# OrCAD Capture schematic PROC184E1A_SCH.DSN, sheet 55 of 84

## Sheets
55 59. MCU GB ETHERNET: size C; title: MCU GB ETHERNET; note: PROC184_SCH
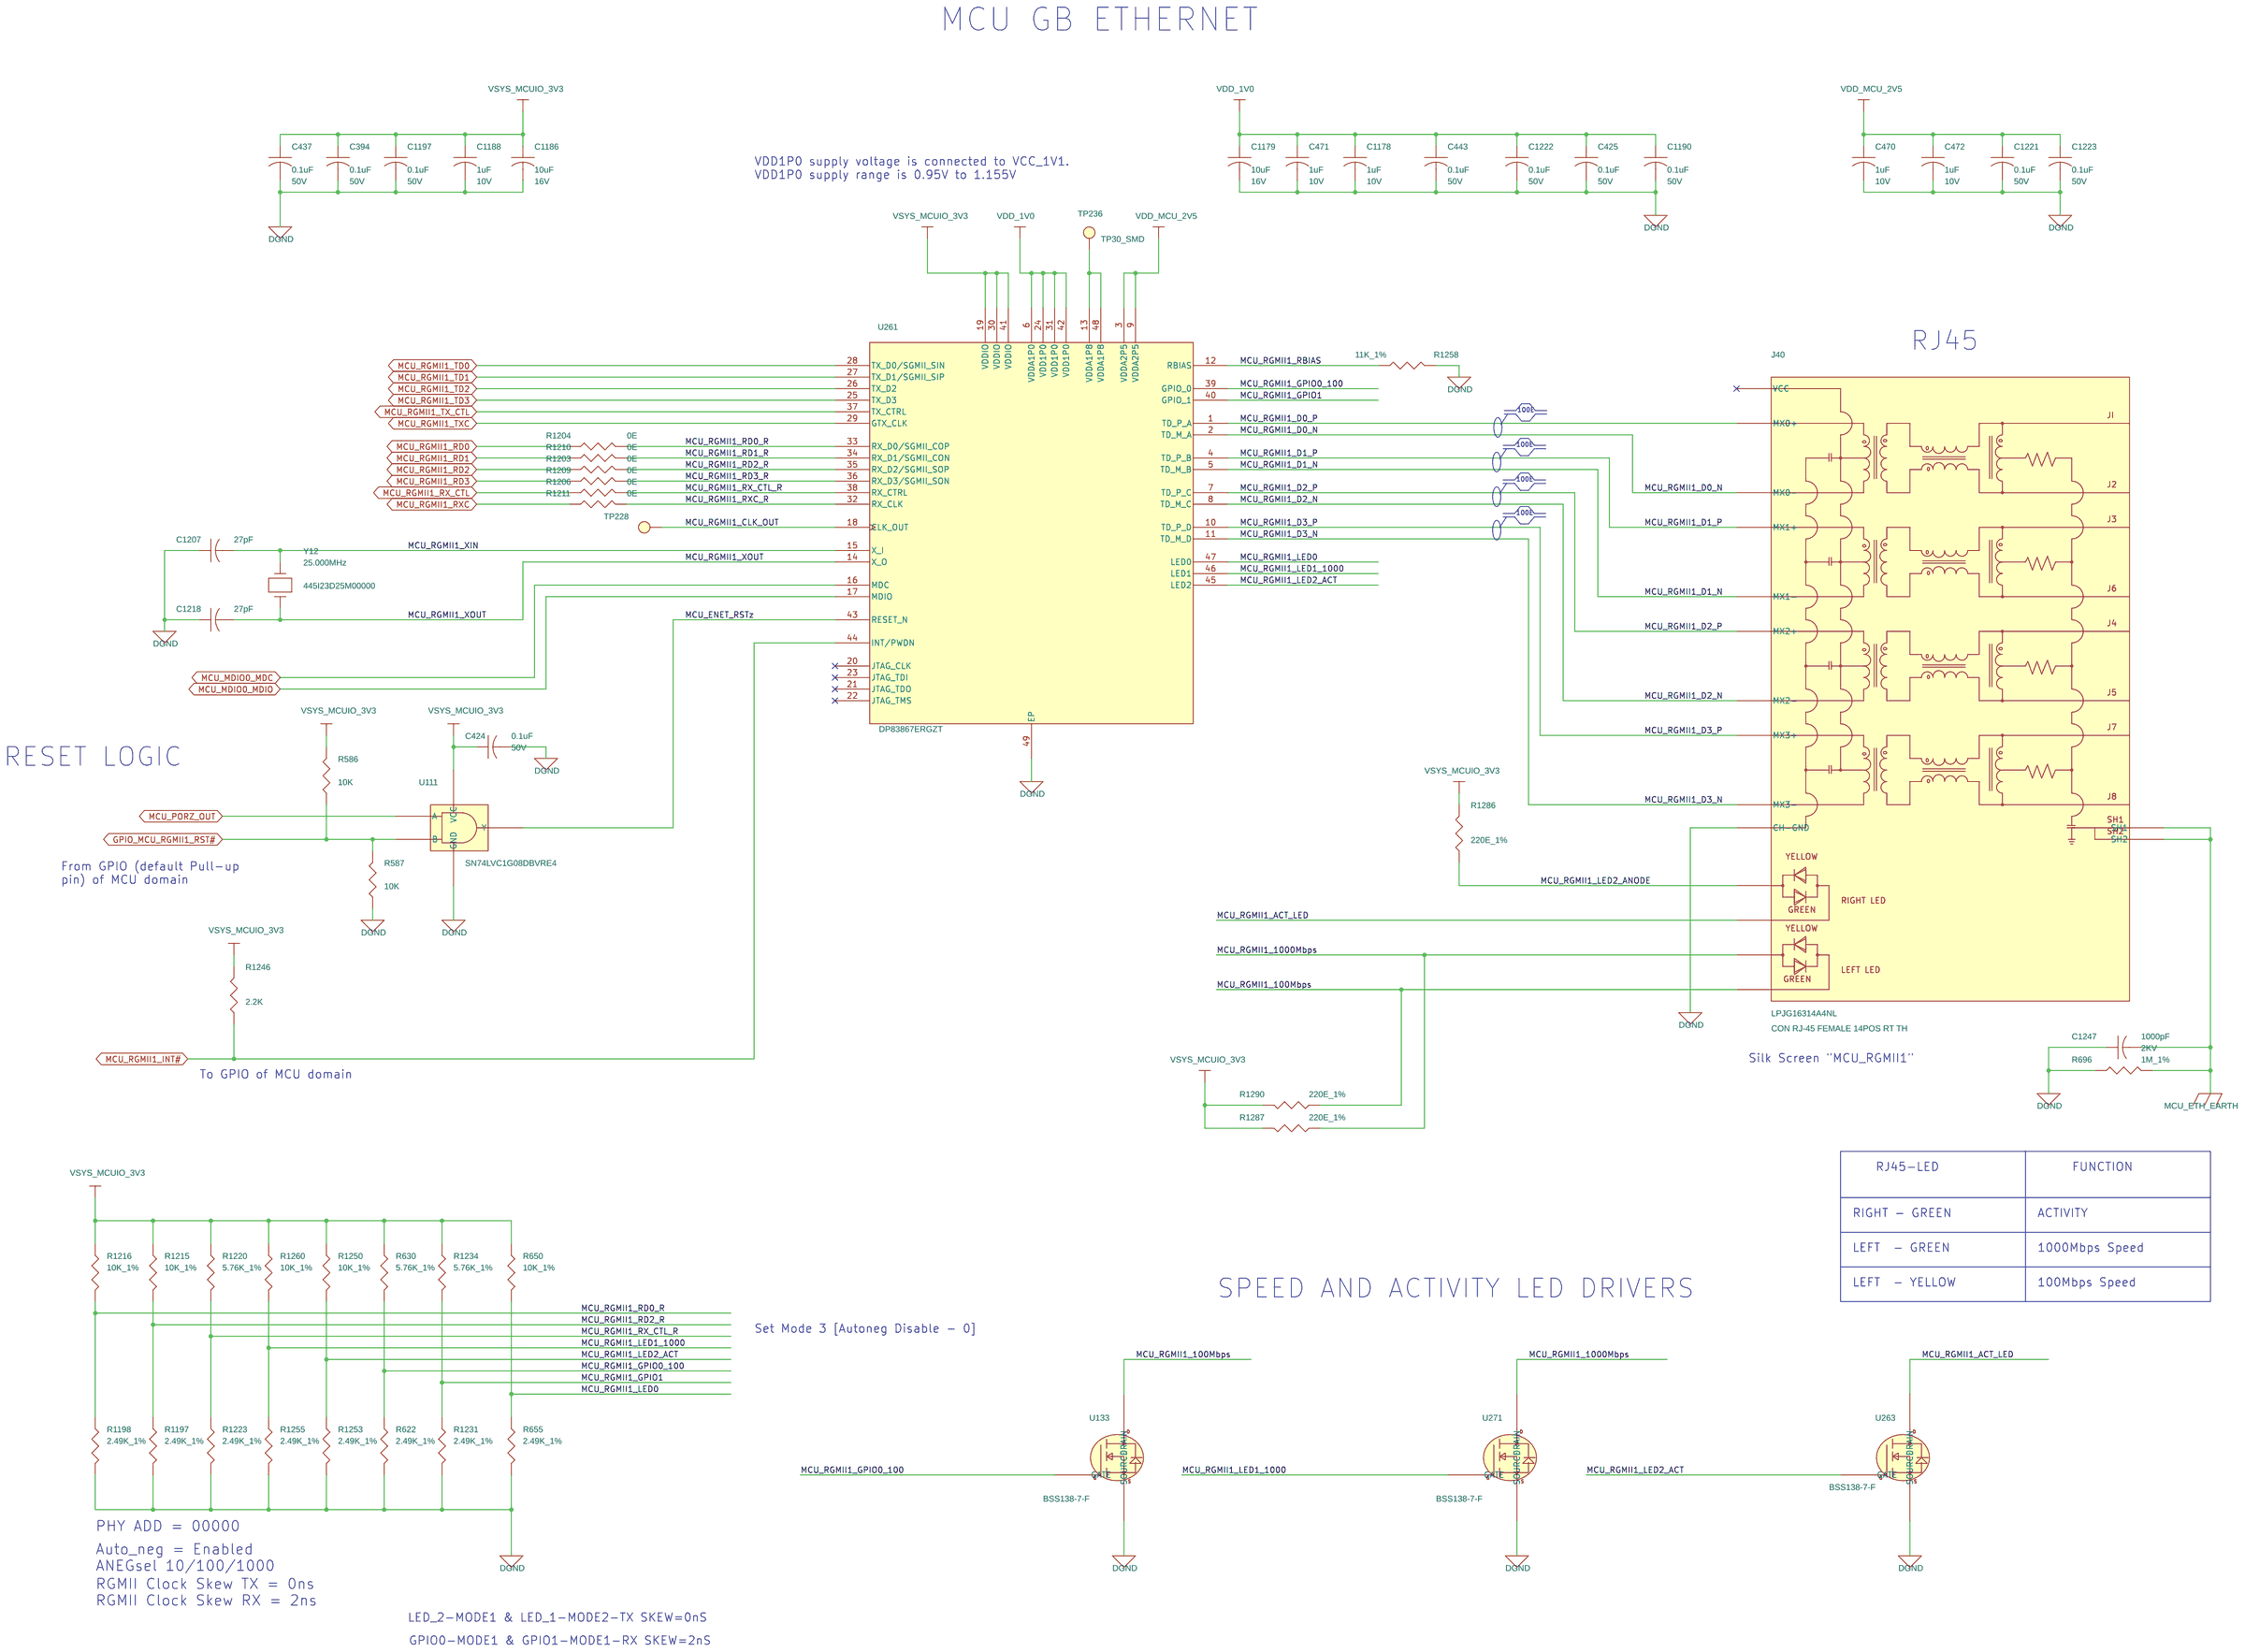
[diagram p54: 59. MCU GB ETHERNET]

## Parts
C394  0.1uF  [CAP0402_0-75]
C424  0.1uF  [CAP0402_0-75]
C425  0.1uF  [CAP0402_0-75]
C437  0.1uF  [CAP0402_0-75]
C443  0.1uF  [CAP0402_0-75]
C470  1uF  [CAP0402_0-75]
C471  1uF  [CAP0402_0-75]
C472  1uF  [CAP0402_0-75]
C1178  1uF  [CAP0402_0-75]
C1179  10uF  [CAP0805_1-5]
C1186  10uF  [CAP0805_1-5]
C1188  1uF  [CAP0402_0-75]
C1190  0.1uF  [CAP0402_0-75]
C1197  0.1uF  [CAP0402_0-75]
C1207  27pF  [CAP0402_0-75]
C1218  27pF  [CAP0402_0-75]
C1221  0.1uF  [CAP0402_0-75]
C1222  0.1uF  [CAP0402_0-75]
C1223  0.1uF  [CAP0402_0-75]
C1247  1000pF  [CAP1206_1-75]
J40  CON_RJ45-14_LPJG16314A4NL  [CON_RJ45-14_LPJG16314A4NL_S_R_T_13-6]
R586  10K  [RES0402_0-5]
R587  10K  [RES0402_0-5]
R622  2.49K_1%  [RES0402_0-5]
R630  5.76K_1%  [RES0402_0-5]
R650  10K_1%  [RES0402_0-5]
R655  2.49K_1%  [RES0402_0-5]
R696  1M_1%  [RES0805_0-75]
R1197  2.49K_1%  [RES0402_0-5]
R1198  2.49K_1%  [RES0402_0-5]
R1203  0E  [RES0201_0-5]
R1204  0E  [RES0201_0-5]
R1206  0E  [RES0201_0-5]
R1209  0E  [RES0201_0-5]
R1210  0E  [RES0201_0-5]
R1211  0E  [RES0201_0-5]
R1215  10K_1%  [RES0402_0-5]
R1216  10K_1%  [RES0402_0-5]
R1220  5.76K_1%  [RES0402_0-5]
R1223  2.49K_1%  [RES0402_0-5]
R1231  2.49K_1%  [RES0402_0-5]
R1234  5.76K_1%  [RES0402_0-5]
R1246  2.2K  [RES0402_0-5]
R1250  10K_1%  [RES0402_0-5]
R1253  2.49K_1%  [RES0402_0-5]
R1255  2.49K_1%  [RES0402_0-5]
R1258  11K_1%  [RES0402_0-5]
R1260  10K_1%  [RES0402_0-5]
R1286  220E_1%  [RES0402_0-5]
R1287  220E_1%  [RES0402_0-5]
R1290  220E_1%  [RES0402_0-5]
TP228  TP30_SMD  [TP30_SMD]
TP236  TP30_SMD  [TP30_SMD]
U111  SN74LVC1G08DBVRE4  [SOT23-5]
U133  BSS138-7-F  [SOT23-123_1-1]
U261  DP83867ERGZT  [VQFN48_19-68_285X285]
U263  BSS138-7-F  [SOT23-123_1-1]
U271  BSS138-7-F  [SOT23-123_1-1]
Y12  25.000MHz  [XTAL_ABM3_205X130_SMD_1-4]

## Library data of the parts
C394 C424 C425 C437 C443 C1190 C1197 C1221-C1223 = CAP: CAP CERAMIC 0.1uF 50V 10% X7R 0402; Automotive Alternate_mfr_name: TDK; Automotive Alternate_mfr_part_number: CGA2B3X7R1H104K050BB; Chkd/date: MANIRAJA/261020; Crtd /date: ALVY/211020; Custom_Duty: 15%; Customs_HS_Code: 85322990; Direct Alternate_mfr_name: TDK; Direct Alternate_mfr_part_number: C1005X7R1H104K050BE; Distributor_name: DIGIKEY; Distributor_part_number: 490-10700-1-ND; Footprint Path: Y:\MIS_DATABASE\Library\ALTIUM_TOOL\PCB_FOOTPRINTS\Altium_Footprint_Lib.PcbLib; Height: 0.55MM; Library Path: Y:\MIS_DATABASE\Library\ALTIUM_TOOL\SCHEMATICS_PARTS\MS_DISCRETE_Library.schlib; Manufacturer: MURATA; Mfr_name: MURATA; Mfr_part_number: GRM155R71H104KE14D; Mistral Part No: 120011100014-R; Package: 0402; Part_type: CAPACITORS\CERAMIC; Project: J7_CP; RoHS: RoHS; Temperature: -55°C+125°C; Tolerance: 10%; Voltage: 50V; Wattage: NA; Weight: 3.1mg; Datasheet: Y:\MIS_DATABASE\DATASHEETS\CAPACITORS\GRM155R71H104KE14.PDF
C470-C472 C1178 C1188 = CAP: CAP CERAMIC 1uF 10V 10% X7S AUTO 0402; Automotive Alternate_mfr_name: TAIYO YUDEN; Automotive Alternate_mfr_part_number: EMK105BJ105KVHF; Chkd/date: MANIRAJA/100918; Crtd /date: ALVY/100918; Custom_Duty: 15%; Customs_HS_Code: 85322990; Direct Alternate_mfr_name: YAGEO AMERICA; Direct Alternate_mfr_part_number: CC0402KRX5R7BB105; Distributor_name: DIGIKEY; Distributor_part_number: 490-13409-1-ND; Footprint Path: Y:\MIS_DATABASE\Library\ALTIUM_TOOL\PCB_FOOTPRINTS\Altium_Footprint_Lib.PcbLib; Height: 0.70MM; Library Path: Y:\MIS_DATABASE\Library\ALTIUM_TOOL\SCHEMATICS_PARTS\MS_DISCRETE_Library.schlib; Manufacturer: TDK CORPORATION; Mfr_name: MURATA; Mfr_part_number: GCM155C71A105KE38D; Mistral Part No: 120018090021-R; Package: 0402; Part_type: CAPACITORS\CERAMIC; Project: SMART-M_SCRIPTALK_PB; RoHS: RoHS; Temperature: -55°C+125°C; Tolerance: 10%; Voltage: 10V; Wattage: NA; Weight: 6mg; Datasheet: Y:\MIS_DATABASE\DATASHEETS\CAPACITORS\MURATA-GCM-SER.PDF
C1179 C1186 = CAP: CAP CERAMIC 10uF 16V 10% X5R 0805; Automotive Alternate_mfr_name: TDK; Automotive Alternate_mfr_part_number: CGA4J1X7S1C106K125AC; Chkd/date: SHREESHAIL/220506; Crtd /date: MAZHAR/150506; Custom_Duty: 15%; Customs_HS_Code: 85322990; Direct Alternate_mfr_name: TDK; Direct Alternate_mfr_part_number: C2012X7S1C106K125AC; Distributor_name: DIGIKEY; Distributor_part_number: 490-3886-1-ND; Footprint Path: Y:\MIS_DATABASE\Library\ALTIUM_TOOL\PCB_FOOTPRINTS\Altium_Footprint_Lib.PcbLib; Height: 1.35MM; Library Path: Y:\MIS_DATABASE\Library\ALTIUM_TOOL\SCHEMATICS_PARTS\MS_DISCRETE_Library.schlib; Manufacturer: MURATA; Mfr_name: MURATA; Mfr_part_number: GRM21BR61C106KE15L; Mistral Part No: 120009030205-R; Package: 0805; Part_type: CAPACITORS\CERAMIC; Project: VOCERA; RoHS: RoHS; Temperature: -55°C+85°C; Tolerance: 10%; Voltage: 16V; Wattage: NA; Weight: 9.5mg; Datasheet: Y:\MIS_DATABASE\DATASHEETS\CAPACITORS\MURATA-GXX-SER_NOV17.PDF
C1207 C1218 = CAP: CAP CERAMIC 27pF 50V 5% C0G(NP0) 0402; Automotive Alternate_mfr_name: TDK; Automotive Alternate_mfr_part_number: CGA2B2C0G1H270J050BA; Chkd/date: MAZHAR/241208; Crtd /date: GEETHA/090606; Custom_Duty: 15%; Customs_HS_Code: 85322990; Direct Alternate_mfr_name: SAMSUNG; Direct Alternate_mfr_part_number: CL05C270JB5NNNC; Distributor_name: DIGIKEY; Distributor_part_number: 311-1019-1-ND; Footprint Path: Y:\MIS_DATABASE\Library\ALTIUM_TOOL\PCB_FOOTPRINTS\Altium_Footprint_Lib.PcbLib; Height: 0.55MM; Library Path: Y:\MIS_DATABASE\Library\ALTIUM_TOOL\SCHEMATICS_PARTS\MS_DISCRETE_Library.schlib; Manufacturer: YAGEO AMERICA; Mfr_name: YAGEO AMERICA; Mfr_part_number: CC0402JRNPO9BN270; Mistral Part No: 120014100024-R; Package: 0402; Part_type: CAPACITORS\CERAMIC; Project: PNAV; RoHS: RoHS; Temperature: -55°C+125°C; Tolerance: 5%; Voltage: 50V; Wattage: NA; Weight: 0.65mg; Datasheet: Y:\MIS_DATABASE\DATASHEETS\CAPACITORS\YACC-NPO.PDF
C1247 = CAP: CAP CERAMIC 1000pF 2KV 10% X7R 1206; Automotive Alternate_mfr_name: KEMET; Automotive Alternate_mfr_part_number: C1206X102KGRACAUTO; Chkd/date: SHREESHAIL/291106; Crtd /date: MAZHAR/281106; Custom_Duty: 15%; Customs_HS_Code: 85322990; Direct Alternate_mfr_name: KEMET; Direct Alternate_mfr_part_number: C1206C102KGRACTU; Distributor_name: DIGIKEY; Distributor_part_number: 478-2956-1-ND; Footprint Path: Y:\MIS_DATABASE\Library\ALTIUM_TOOL\PCB_FOOTPRINTS\Altium_Footprint_Lib.PcbLib; Height: 1.52MM; Library Path: Y:\MIS_DATABASE\Library\ALTIUM_TOOL\SCHEMATICS_PARTS\MS_DISCRETE_Library.schlib; Manufacturer: AVX CORPORATION; Mfr_name: AVX CORPORATION; Mfr_part_number: 1206GC102KAT1A; Mistral Part No: 120015080006-R; Package: 1206; Part_type: CAPACITORS\CERAMIC; Project: ADR1B; RoHS: RoHS; Temperature: -55°C+125°C; Tolerance: 10%; Voltage: 2KV; Wattage: NA; Weight: 16.2mg; Datasheet: Y:\MIS_DATABASE\DATASHEETS\CAPACITORS\AVX_HV-MLC.PDF
J40 = CON_RJ45-14_LPJG16314A4NL: CON RJ-45 FEMALE 14POS RT TH; Chkd/date: VASANTHA/150714; Crtd /date: BALACHANDAR/120614; Custom_Duty: 24%; Customs_HS_Code: 85369090; Distributor_name: NA; Distributor_part_number: NA; Footprint Path: Y:\MIS_DATABASE\Library\ALTIUM_TOOL\PCB_FOOTPRINTS\Altium_Footprint_Lib.PcbLib; Height: 13.60MM; Library Path: Y:\MIS_DATABASE\Library\ALTIUM_TOOL\SCHEMATICS_PARTS\MS_CONNECTOR_Library.schlib; Manufacturer: LINK-PP; Mfr_name: LINK-PP; Mfr_part_number: LPJG16314A4NL; Mistral Part No: 150014060029-R; Package: THRU-HOLE; Part_type: CONNECTOR\JACK; Project: AEGIS; RoHS: RoHS; Temperature: -0°C+70°C; Tolerance: NA; Voltage: NA; Wattage: NA; Weight: NA; Datasheet: Y:\MIS_DATABASE\DATASHEETS\CONNECTORS\LPJG16314A4NL.PDF
R586 = RESISTOR: RES 10K 1/16W 5% 0402; Chkd/date: VASANTHA/061216; Crtd /date: MAZHAR/230805; Custom_Duty: 15%; Customs_HS_Code: 85332119; Distributor_name: DIGIKEY; Distributor_part_number: 311-10KJRCT-ND; Footprint Path: Y:\MIS_DATABASE\Library\ALTIUM_TOOL\PCB_FOOTPRINTS\Altium_Footprint_Lib.PcbLib; Height: 0.40MM; Library Path: Y:\MIS_DATABASE\Library\ALTIUM_TOOL\SCHEMATICS_PARTS\MS_DISCRETE_Library.schlib; Manufacturer: YAGEO AMERICA; Mfr_name: YAGEO AMERICA; Mfr_part_number: RC0402JR-0710KL; Mistral Part No: 110011060021-R; Package: 0402; Part_type: RESISTORS\FIXED; Project: HSE; RoHS: RoHS; Temperature: -55°C+155°C; Tolerance: 5%; Voltage: NA; Wattage: 1/16W; Weight: 0.65mg; Datasheet: Y:\MIS_DATABASE\DATASHEETS\RESISTORS\RCXXXXL-SER_MAR18.PDF
R587 = RESISTOR: RES 10K 1/16W 5% 0402; Assembly_Instruction: DNI; Chkd/date: VASANTHA/061216; Crtd /date: MAZHAR/230805; Custom_Duty: 15%; Customs_HS_Code: 85332119; Distributor_name: DIGIKEY; Distributor_part_number: 311-10KJRCT-ND; Footprint Path: Y:\MIS_DATABASE\Library\ALTIUM_TOOL\PCB_FOOTPRINTS\Altium_Footprint_Lib.PcbLib; Height: 0.40MM; Library Path: Y:\MIS_DATABASE\Library\ALTIUM_TOOL\SCHEMATICS_PARTS\MS_DISCRETE_Library.schlib; Manufacturer: YAGEO AMERICA; Mfr_name: YAGEO AMERICA; Mfr_part_number: RC0402JR-0710KL; Mistral Part No: 110011060021-R; Package: 0402; Part_type: RESISTORS\FIXED; Project: HSE; RoHS: RoHS; Temperature: -55°C+155°C; Tolerance: 5%; Voltage: NA; Wattage: 1/16W; Weight: 0.65mg; Datasheet: Y:\MIS_DATABASE\DATASHEETS\RESISTORS\RCXXXXL-SER_MAR18.PDF
R622 R655 R1197 R1198 R1231 R1253 = RESISTOR: RES 2.49K 1/16W 1% 0402; Assembly_Instruction: DNI; Chkd/date: VASANTHA/270516; Crtd /date: VASANTHA/270516; Custom_Duty: 15%; Customs_HS_Code: 85332119; Distributor_name: DIGIKEY; Distributor_part_number: 311-2.49KLRCT-ND; Footprint Path: Y:\MIS_DATABASE\Library\ALTIUM_TOOL\PCB_FOOTPRINTS\Altium_Footprint_Lib.PcbLib; Height: 0.40MM; Library Path: Y:\MIS_DATABASE\Library\ALTIUM_TOOL\SCHEMATICS_PARTS\MS_DISCRETE_Library.schlib; Manufacturer: YAGEO AMERICA; Mfr_name: YAGEO AMERICA; Mfr_part_number: RC0402FR-072K49L; Mistral Part No: 110016050020-R; Package: 0402; Part_type: RESISTORS\FIXED; Project: TMDXCSKCC; RoHS: RoHS; Temperature: -55°C+155°C; Tolerance: 1%; Voltage: NA; Wattage: 1/16W; Weight: 0.65mg; Datasheet: Y:\MIS_DATABASE\DATASHEETS\RESISTORS\RCXXXXL-SER_MAR18.PDF
R630 R1234 = RESISTOR: RES 5.76K 1/10W 1% 0402; Assembly_Instruction: DNI; Chkd/date: MAZHAR/150709; Crtd /date: USMAN/220808; Custom_Duty: 15%; Customs_HS_Code: 85332119; Distributor_name: DIGIKEY; Distributor_part_number: P5.76KLCT-ND; Footprint Path: Y:\MIS_DATABASE\Library\ALTIUM_TOOL\PCB_FOOTPRINTS\Altium_Footprint_Lib.PcbLib; Height: 0.40MM; Library Path: Y:\MIS_DATABASE\Library\ALTIUM_TOOL\SCHEMATICS_PARTS\MS_DISCRETE_Library.schlib; Manufacturer: PANASONIC-ECG; Mfr_name: PANASONIC-ECG; Mfr_part_number: ERJ-2RKF5761X; Mistral Part No: 110009030945-R; Package: 0402; Part_type: RESISTORS\FIXED; Project: CPB; RoHS: RoHS; Temperature: -55°C+155°C; Tolerance: 1%; Voltage: NA; Wattage: 1/10W; Weight: 0.8mg; Datasheet: Y:\MIS_DATABASE\DATASHEETS\RESISTORS\PAN-ERJSER_NOV17.PDF
R650 R1215 R1216 R1250 = RESISTOR: RES 10K 1/16W 1% 0402; Assembly_Instruction: DNI; Chkd/date: VASANTHA/201216; Crtd /date: GEETHA/290506; Custom_Duty: 15%; Customs_HS_Code: 85332119; Distributor_name: DIGIKEY; Distributor_part_number: 311-10.0KLRTR-ND; Footprint Path: Y:\MIS_DATABASE\Library\ALTIUM_TOOL\PCB_FOOTPRINTS\Altium_Footprint_Lib.PcbLib; Height: 0.40MM; Library Path: Y:\MIS_DATABASE\Library\ALTIUM_TOOL\SCHEMATICS_PARTS\MS_DISCRETE_Library.schlib; Manufacturer: YAGEO AMERICA; Mfr_name: YAGEO AMERICA; Mfr_part_number: RC0402FR-0710KL; Mistral Part No: 110015090015-R; Package: 0402; Part_type: RESISTORS\FIXED; Project: VOCERA; RoHS: RoHS; Temperature: -55°C+155°C; Tolerance: 1%; Voltage: NA; Wattage: 1/16W; Weight: 0.65mg; Datasheet: Y:\MIS_DATABASE\DATASHEETS\RESISTORS\RCXXXXL-SER_MAR18.PDF
R696 = RESISTOR: RES 1M 1/8W 1% 0805; Chkd/date: VASANTHA/150514; Crtd /date: BALACHANDAR/150514; Custom_Duty: 15%; Customs_HS_Code: 85332119; Distributor_name: DIGIKEY; Distributor_part_number: P1.00MCCT-ND; Footprint Path: Y:\MIS_DATABASE\Library\ALTIUM_TOOL\PCB_FOOTPRINTS\Altium_Footprint_Lib.PcbLib; Height: 0.70MM; Library Path: Y:\MIS_DATABASE\Library\ALTIUM_TOOL\SCHEMATICS_PARTS\MS_DISCRETE_Library.schlib; Manufacturer: PANASONIC-ECG; Mfr_name: PANASONIC-ECG; Mfr_part_number: ERJ-6ENF1004V; Mistral Part No: 110014100002-R; Package: 0805; Part_type: RESISTORS\FIXED; Project: HUMANWARE_PHOENIX; RoHS: RoHS; Temperature: -55°C+155°C; Tolerance: 1%; Voltage: NA; Wattage: 1/8W; Weight: 4mg; Datasheet: Y:\MIS_DATABASE\DATASHEETS\RESISTORS\PAN-ERJSER_NOV17.PDF
R1203 R1204 R1206 R1209-R1211 = RESISTOR: RES 0E 1/20W 5% 0201; Chkd/date: NAVEED/301214; Crtd /date: MUDDU/120710; Custom_Duty: 15%; Customs_HS_Code: 85332119; Distributor_name: DIGIKEY; Distributor_part_number: 311-0.0NCT-ND; Footprint Path: Y:\MIS_DATABASE\Library\ALTIUM_TOOL\PCB_FOOTPRINTS\Altium_Footprint_Lib.PcbLib; Height: 0.26MM; Library Path: Y:\MIS_DATABASE\Library\ALTIUM_TOOL\SCHEMATICS_PARTS\MS_DISCRETE_Library.schlib; Manufacturer: YAGEO AMERICA; Mfr_name: YAGEO AMERICA; Mfr_part_number: RC0201JR-070RL; Mistral Part No: 110010070067-R; Package: 0201; Part_type: RESISTORS\FIXED; Project: PB_BUGBASE; RoHS: RoHS; Temperature: -55°C+125°C; Tolerance: 5%; Voltage: NA; Wattage: 1/20W; Weight: 0.17mg; Datasheet: Y:\MIS_DATABASE\DATASHEETS\RESISTORS\RCXXXXL-SER_MAR18.PDF
R1220 = RESISTOR: RES 5.76K 1/10W 1% 0402; Chkd/date: MAZHAR/150709; Crtd /date: USMAN/220808; Custom_Duty: 15%; Customs_HS_Code: 85332119; Distributor_name: DIGIKEY; Distributor_part_number: P5.76KLCT-ND; Footprint Path: Y:\MIS_DATABASE\Library\ALTIUM_TOOL\PCB_FOOTPRINTS\Altium_Footprint_Lib.PcbLib; Height: 0.40MM; Library Path: Y:\MIS_DATABASE\Library\ALTIUM_TOOL\SCHEMATICS_PARTS\MS_DISCRETE_Library.schlib; Manufacturer: PANASONIC-ECG; Mfr_name: PANASONIC-ECG; Mfr_part_number: ERJ-2RKF5761X; Mistral Part No: 110009030945-R; Package: 0402; Part_type: RESISTORS\FIXED; Project: CPB; RoHS: RoHS; Temperature: -55°C+155°C; Tolerance: 1%; Voltage: NA; Wattage: 1/10W; Weight: 0.8mg; Datasheet: Y:\MIS_DATABASE\DATASHEETS\RESISTORS\PAN-ERJSER_NOV17.PDF
R1223 R1255 = RESISTOR: RES 2.49K 1/16W 1% 0402; Chkd/date: VASANTHA/270516; Crtd /date: VASANTHA/270516; Custom_Duty: 15%; Customs_HS_Code: 85332119; Distributor_name: DIGIKEY; Distributor_part_number: 311-2.49KLRCT-ND; Footprint Path: Y:\MIS_DATABASE\Library\ALTIUM_TOOL\PCB_FOOTPRINTS\Altium_Footprint_Lib.PcbLib; Height: 0.40MM; Library Path: Y:\MIS_DATABASE\Library\ALTIUM_TOOL\SCHEMATICS_PARTS\MS_DISCRETE_Library.schlib; Manufacturer: YAGEO AMERICA; Mfr_name: YAGEO AMERICA; Mfr_part_number: RC0402FR-072K49L; Mistral Part No: 110016050020-R; Package: 0402; Part_type: RESISTORS\FIXED; Project: TMDXCSKCC; RoHS: RoHS; Temperature: -55°C+155°C; Tolerance: 1%; Voltage: NA; Wattage: 1/16W; Weight: 0.65mg; Datasheet: Y:\MIS_DATABASE\DATASHEETS\RESISTORS\RCXXXXL-SER_MAR18.PDF
R1246 = RESISTOR: RES 2.2K 1/16W 5% 0402; Chkd/date: VASANTHA/061216; Crtd /date: BAVISH/021210; Custom_Duty: 15%; Customs_HS_Code: 85332119; Distributor_name: DIGIKEY; Distributor_part_number: 311-2.2KJRCT-ND; Footprint Path: Y:\MIS_DATABASE\Library\ALTIUM_TOOL\PCB_FOOTPRINTS\Altium_Footprint_Lib.PcbLib; Height: 0.40MM; Library Path: Y:\MIS_DATABASE\Library\ALTIUM_TOOL\SCHEMATICS_PARTS\MS_DISCRETE_Library.schlib; Manufacturer: YAGEO AMERICA; Mfr_name: YAGEO AMERICA; Mfr_part_number: RC0402JR-072K2L; Mistral Part No: 110010120018-R; Package: 0402; Part_type: RESISTORS\FIXED; Project: TE4; RoHS: RoHS; Temperature: -55°C+155°C; Tolerance: 5%; Voltage: NA; Wattage: 1/16W; Weight: 0.65mg; Datasheet: Y:\MIS_DATABASE\DATASHEETS\RESISTORS\RCXXXXL-SER_MAR18.PDF
R1258 = RESISTOR: RES 11K 1/16W 1% 0402; Chkd/date: VASANTHA/251115; Crtd /date: VASANTHA/251115; Custom_Duty: 15%; Customs_HS_Code: 85332119; Distributor_name: DIGIKEY; Distributor_part_number: 311-11.0KLRCT-ND; Footprint Path: Y:\MIS_DATABASE\Library\ALTIUM_TOOL\PCB_FOOTPRINTS\Altium_Footprint_Lib.PcbLib; Height: 0.40MM; Library Path: Y:\MIS_DATABASE\Library\ALTIUM_TOOL\SCHEMATICS_PARTS\MS_DISCRETE_Library.schlib; Manufacturer: YAGEO AMERICA; Mfr_name: YAGEO AMERICA; Mfr_part_number: RC0402FR-0711KL; Mistral Part No: 110015110012-R; Package: 0402; Part_type: RESISTORS\FIXED; Project: TI_VLAN_SWITCH; RoHS: RoHS; Temperature: -55°C+155°C; Tolerance: 1%; Voltage: NA; Wattage: 1/16W; Weight: 0.65mg; Datasheet: Y:\MIS_DATABASE\DATASHEETS\RESISTORS\RCXXXXL-SER_MAR18.PDF
R1260 = RESISTOR: RES 10K 1/16W 1% 0402; Chkd/date: VASANTHA/201216; Crtd /date: GEETHA/290506; Custom_Duty: 15%; Customs_HS_Code: 85332119; Distributor_name: DIGIKEY; Distributor_part_number: 311-10.0KLRTR-ND; Footprint Path: Y:\MIS_DATABASE\Library\ALTIUM_TOOL\PCB_FOOTPRINTS\Altium_Footprint_Lib.PcbLib; Height: 0.40MM; Library Path: Y:\MIS_DATABASE\Library\ALTIUM_TOOL\SCHEMATICS_PARTS\MS_DISCRETE_Library.schlib; Manufacturer: YAGEO AMERICA; Mfr_name: YAGEO AMERICA; Mfr_part_number: RC0402FR-0710KL; Mistral Part No: 110015090015-R; Package: 0402; Part_type: RESISTORS\FIXED; Project: VOCERA; RoHS: RoHS; Temperature: -55°C+155°C; Tolerance: 1%; Voltage: NA; Wattage: 1/16W; Weight: 0.65mg; Datasheet: Y:\MIS_DATABASE\DATASHEETS\RESISTORS\RCXXXXL-SER_MAR18.PDF
R1286 R1287 R1290 = RESISTOR: RES 220E 1/16W 1% 0402; Chkd/date: MANIRAJA/130917; Crtd /date: MANIRAJA/130917; Custom_Duty: 15%; Customs_HS_Code: 85332119; Distributor_name: DIGIKEY; Distributor_part_number: 311-220LRCT-ND; Footprint Path: Y:\MIS_DATABASE\Library\ALTIUM_TOOL\PCB_FOOTPRINTS\Altium_Footprint_Lib.PcbLib; Height: 0.40MM; Library Path: Y:\MIS_DATABASE\Library\ALTIUM_TOOL\SCHEMATICS_PARTS\MS_DISCRETE_Library.schlib; Manufacturer: YAGEO AMERICA; Mfr_name: YAGEO AMERICA; Mfr_part_number: RC0402FR-07220RL; Mistral Part No: 110019040169-R; Package: 0402; Part_type: RESISTORS\FIXED; Project: TI_SVB_MAXWELL_DUT; RoHS: RoHS; Temperature: -55°C+155°C; Tolerance: 1%; Voltage: NA; Wattage: 1/16W; Weight: 0.65mg; Datasheet: Y:\MIS_DATABASE\DATASHEETS\RESISTORS\RCXXXXL-SER_MAR18.PDF
TP228 TP236 = TESTPOINT: TESTPOINT CIR 30 SMD; Chkd/date: SHREESHAIL/171006; Crtd /date: MAZHAR/171006; Custom_Duty: NA; Customs_HS_Code: NA; Distributor_name: NA; Distributor_part_number: NA; Footprint Path: Y:\MIS_DATABASE\Library\ALTIUM_TOOL\PCB_FOOTPRINTS\Altium_Footprint_Lib.PcbLib; Height: NA; Library Path: Y:\MIS_DATABASE\Library\ALTIUM_TOOL\SCHEMATICS_PARTS\MS_DISCRETE_Library.schlib; MECHANICAL 3D STEP FILE: NA; Manufacturer: LOCAL; Mfr_name: LOCAL; Mistral Part No: 130009030930; Package: SMD; Project: BT MODULE_CSRBC04; RoHS: NA; Temperature: NA; Tolerance: NA; Voltage: NA; Wattage: NA; Weight: NA; Datasheet: NA
U111 = SN74LVC1G08DBVRE4_SOT23-5: IC SINGLE 2-INPUT POSITIVE AND GATE SOT23-5; Automotive Alternate_mfr_name: TEXAS INSTRUMENTS; Automotive Alternate_mfr_part_number: SN74LVC1G08QDBVRQ1; Chkd/date: SUHAS/221010; Crtd /date: USMAN/151008; Custom_Duty: 15%; Customs_HS_Code: 85423100; Distributor_name: DIGIKEY; Distributor_part_number: SN74LVC1G08DBVRE4-ND; Height: 1.45MM; Manufacturer: TEXAS INSTRUMENTS; Mfr_name: TEXAS INSTRUMENTS; Mistral Part No: 141009060026-R; Part_type: ICS\DIGITAL\GATES; Project: KHAN_MAIN; RoHS: Sb/ Br FREE; Temperature: -40°C+85°C; Datasheet: Y:\MIS_DATABASE\DATASHEETS\ICS\DIGITAL\GATES\SN74LVC1G08.PDF
U133 U263 U271 = MOSFET_2N7002_SOT23: IC MOSFET N-CHANNEL 50V 200mA SOT23-123; Chkd/date: MANIRAJA/190618; Crtd /date: USMAN/240709; Custom_Duty: 15%; Customs_HS_Code: 85423100; Distributor_name: DIGIKEY; Distributor_part_number: BSS138-FDICT-ND; Footprint Path: Y:\MIS_DATABASE\Library\ALTIUM_TOOL\PCB_FOOTPRINTS\Altium_Footprint_Lib.PcbLib; Height: 1.10MM; Library Path: Y:\MIS_DATABASE\Library\ALTIUM_TOOL\SCHEMATICS_PARTS\MS_MOSFET_Library.schlib; Manufacturer: DIODES INC; Mfr_name: DIODES INC; Mistral Part No: 142009070019-R; Package: SOT23-123; Part_type: ICS\POWER\MOSFET; Project: KHAN_MAIN; RoHS: RoHS; Temperature: -55°C+150°C; Tolerance: NA; Voltage: 50V; Wattage: 300mW; Weight: 8mg; Datasheet: Y:\MIS_DATABASE\DATASHEETS\DISCRETES\TRANSISTORS_FETS\BSS138.PDF
U261 = DP83867ERGZT_VQFN48: IC SMALL FORM FACTOR 10/100/1000 Mb/s ETHERNET PHY LAYER TRANSCEIVER VQFN48; Chkd/date: VASANTHA/251115; Crtd /date: VASANTHA/251115; Custom_Duty: 15%; Customs_HS_Code: 85423100; Distributor_name: DIGIKEY; Distributor_part_number: 296-43254-1-ND; Height: 1.00MM; Manufacturer: TEXAS INSTRUMENTS; Mfr_name: TEXAS INSTRUMENTS; Mistral Part No: 143015110004-R; Package: VQFN48; Part_type: ICS\TELECOM\TRANSCEIVER; Project: TI_VLAN_SWITCH; RoHS: RoHS; Temperature: -40°C+105°C; Tolerance: NA; Voltage: NA; Wattage: NA; Weight: NA; Datasheet: Y:\MIS_DATABASE\DATASHEETS\ICS\DIGITAL\BUSTRANSCEIVER\DP83867.PDF
Y12 = CRY: CRY 25.000MHz 18pF SMD; Chkd/date: VASANTHA/110316; Crtd /date: JEBRAN/090216; Custom_Duty: 24%; Customs_HS_Code: 85439000; Distributor_name: DIGIKEY; Distributor_part_number: CTX1175CT-ND; Footprint Path: Y:\MIS_DATABASE\Library\ALTIUM_TOOL\PCB_FOOTPRINTS\Altium_Footprint_Lib.PcbLib; Height: 1.35MM; Library Path: Y:\MIS_DATABASE\Library\ALTIUM_TOOL\SCHEMATICS_PARTS\MS_DISCRETE_Library.schlib; Manufacturer: CTS; Mfr_name: CTS; Mfr_part_number: 445I23D25M00000; Mistral Part No: 130016020016-R; Package: SMD; Part_type: CRYSTAL; Project: PDI_MINIPCB; RoHS: RoHS; Temperature: -40°C+85°C; Tolerance: NA; Voltage: NA; Wattage: NA; Weight: 50mg; Datasheet: Y:\MIS_DATABASE\DATASHEETS\MISC\CRY_OSC\445.PDF

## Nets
DGND: C394.2 C424.2 C425.2 C437.2 C443.2 C470.2 C471.2 C472.2 C1178.2 C1179.2 C1186.2 C1188.2 C1190.2 C1197.2 C1207.1 C1218.1 C1221.2 C1222.2 C1223.2 C1247.1 J40.1(CH-GND) R587.1 R622.2 R655.2 R696.1 R1197.2 R1198.2 R1223.2 R1231.2 R1253.2 R1255.2 R1258.1 U111.3(GND) U133.2(SOURCE) U261.49(EP) U263.2(SOURCE) U271.2(SOURCE) ; also on sheet 11 12 13 14 15 16 17 18 20 21 22 23 24 25 26 27 28 29 30 31 32 33 34 35 36 37 38 39 40 41 42 43 44 45 46 47 48 49 50 51 52 53 54 56 57 58 59 60 61 62 63 64 65 66 67 68 69 70 71 72 73 76 77 78 79 81 82 83 84
VDD_1V0: C425.1 C443.1 C471.1 C1178.1 C1179.1 C1190.1 C1222.1 U261.6(VDDA1P0) U261.24(VDD1P0) U261.31(VDD1P0) U261.42(VDD1P0) ; also on sheet 68
VDD_MCU_2V5: C470.1 C472.1 C1221.1 C1223.1 U261.3(VDDA2P5) U261.9(VDDA2P5) ; also on sheet 68
GPIO_MCU_RGMII1_RST#: R586.1 R587.2 U111.2(B) ; also on sheet 18
MCU_ENET_RSTz: U111.4(Y) U261.43(RESET_N)
MCU_ETH_EARTH: C1247.2 J40.15(SH1) J40.16(SH2) R696.2 ; also on sheet 56
MCU_MDIO0_MDC: U261.16(MDC) ; also on sheet 21
MCU_MDIO0_MDIO: U261.17(MDIO) ; also on sheet 21
MCU_PORZ_OUT: U111.1(A) ; also on sheet 18 37 69
MCU_RGMII1_100Mbps: J40.14 R1290.1 U133.3(DRAIN)
MCU_RGMII1_1000Mbps: J40.13 R1287.1 U271.3(DRAIN)
MCU_RGMII1_ACT_LED: J40.12 U263.3(DRAIN)
MCU_RGMII1_CLK_OUT: TP228.1(TP) U261.18(CLK_OUT)
MCU_RGMII1_D0_N: J40.10(MX0-) U261.2(TD_M_A)
MCU_RGMII1_D0_P: J40.9(MX0+) U261.1(TD_P_A)
MCU_RGMII1_D1_N: J40.8(MX1-) U261.5(TD_M_B)
MCU_RGMII1_D1_P: J40.7(MX1+) U261.4(TD_P_B)
MCU_RGMII1_D2_N: J40.6(MX2-) U261.8(TD_M_C)
MCU_RGMII1_D2_P: J40.5(MX2+) U261.7(TD_P_C)
MCU_RGMII1_D3_N: J40.4(MX3-) U261.11(TD_M_D)
MCU_RGMII1_D3_P: J40.3(MX3+) U261.10(TD_P_D)
MCU_RGMII1_GPIO0_100: R622.1 R630.2 U133.1(GATE) U261.39(GPIO_0)
MCU_RGMII1_GPIO1: R1231.1 R1234.2 U261.40(GPIO_1)
MCU_RGMII1_INT#: R1246.1 U261.44(INT/PWDN) ; also on sheet 18
MCU_RGMII1_LED0: R650.2 R655.1 U261.47(LED0)
MCU_RGMII1_LED1_1000: R1255.1 R1260.2 U261.46(LED1) U271.1(GATE)
MCU_RGMII1_LED2_ACT: R1250.2 R1253.1 U261.45(LED2) U263.1(GATE)
MCU_RGMII1_LED2_ANODE: J40.11 R1286.1
MCU_RGMII1_RBIAS: R1258.2 U261.12(RBIAS)
MCU_RGMII1_RD0: R1204.1 ; also on sheet 21
MCU_RGMII1_RD0_R: R1198.1 R1204.2 R1216.2 U261.33(RX_D0/SGMII_COP)
MCU_RGMII1_RD1: R1210.1 ; also on sheet 21
MCU_RGMII1_RD1_R: R1210.2 U261.34(RX_D1/SGMII_CON)
MCU_RGMII1_RD2: R1203.1 ; also on sheet 21
MCU_RGMII1_RD2_R: R1197.1 R1203.2 R1215.2 U261.35(RX_D2/SGMII_SOP)
MCU_RGMII1_RD3: R1209.1 ; also on sheet 21
MCU_RGMII1_RD3_R: R1209.2 U261.36(RX_D3/SGMII_SON)
MCU_RGMII1_RX_CTL: R1206.1 ; also on sheet 21
MCU_RGMII1_RX_CTL_R: R1206.2 R1220.2 R1223.1 U261.38(RX_CTRL)
MCU_RGMII1_RXC: R1211.1 ; also on sheet 21
MCU_RGMII1_RXC_R: R1211.2 U261.32(RX_CLK)
MCU_RGMII1_TD0: U261.28(TX_D0/SGMII_SIN) ; also on sheet 21
MCU_RGMII1_TD1: U261.27(TX_D1/SGMII_SIP) ; also on sheet 21
MCU_RGMII1_TD2: U261.26(TX_D2) ; also on sheet 21
MCU_RGMII1_TD3: U261.25(TX_D3) ; also on sheet 21
MCU_RGMII1_TX_CTL: U261.37(TX_CTRL) ; also on sheet 21
MCU_RGMII1_TXC: U261.29(GTX_CLK) ; also on sheet 21
MCU_RGMII1_XIN: C1207.2 U261.15(X_I) Y12.2
MCU_RGMII1_XOUT: C1218.2 U261.14(X_O) Y12.1
VSYS_MCUIO_3V3: C394.1 C424.1 C437.1 C1186.1 C1188.1 C1197.1 R586.2 R630.1 R650.1 R1215.1 R1216.1 R1220.1 R1234.1 R1246.2 R1250.1 R1260.1 R1286.2 R1287.2 R1290.2 U111.5(VCC) U261.19(VDDIO) U261.30(VDDIO) U261.41(VDDIO) ; also on sheet 16 17 18 21 22 23 35 36 43 44 48 49 62 65 68 75
N24020919: TP236.1(TP) U261.13(VDDA1P8) U261.48(VDDA1P8)

Not connected (* = marked no-connect by the designer): J40 2(VCC)*; U261 20(JTAG_CLK)* 21(JTAG_TDO)* 22(JTAG_TMS)* 23(JTAG_TDI)*

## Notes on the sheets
sheet 55
- MCU GB ETHERNET
- VDD1P0 supply voltage is connected to VCC_1V1.
  VDD1P0 supply range is 0.95V to 1.155V
- RJ45
- 100E
- 100E
- 100E
- 100E
- RESET LOGIC
- From GPIO (default Pull-up
  pin) of MCU domain
- Silk Screen "MCU_RGMII1"
- To GPIO of MCU domain
- RJ45-LED
- FUNCTION
- RIGHT - GREEN
- ACTIVITY
- LEFT  - GREEN
- 1000Mbps Speed
- SPEED AND ACTIVITY LED DRIVERS
- LEFT  - YELLOW
- 100Mbps Speed
- Set Mode 3 [Autoneg Disable - 0]
- PHY ADD = 00000
- Auto_neg = Enabled
  ANEGsel 10/100/1000
- RGMII Clock Skew TX = 0ns
  RGMII Clock Skew RX = 2ns
- LED_2-MODE1 & LED_1-MODE2-TX SKEW=0nS
- GPIO0-MODE1 & GPIO1-MODE1-RX SKEW=2nS
